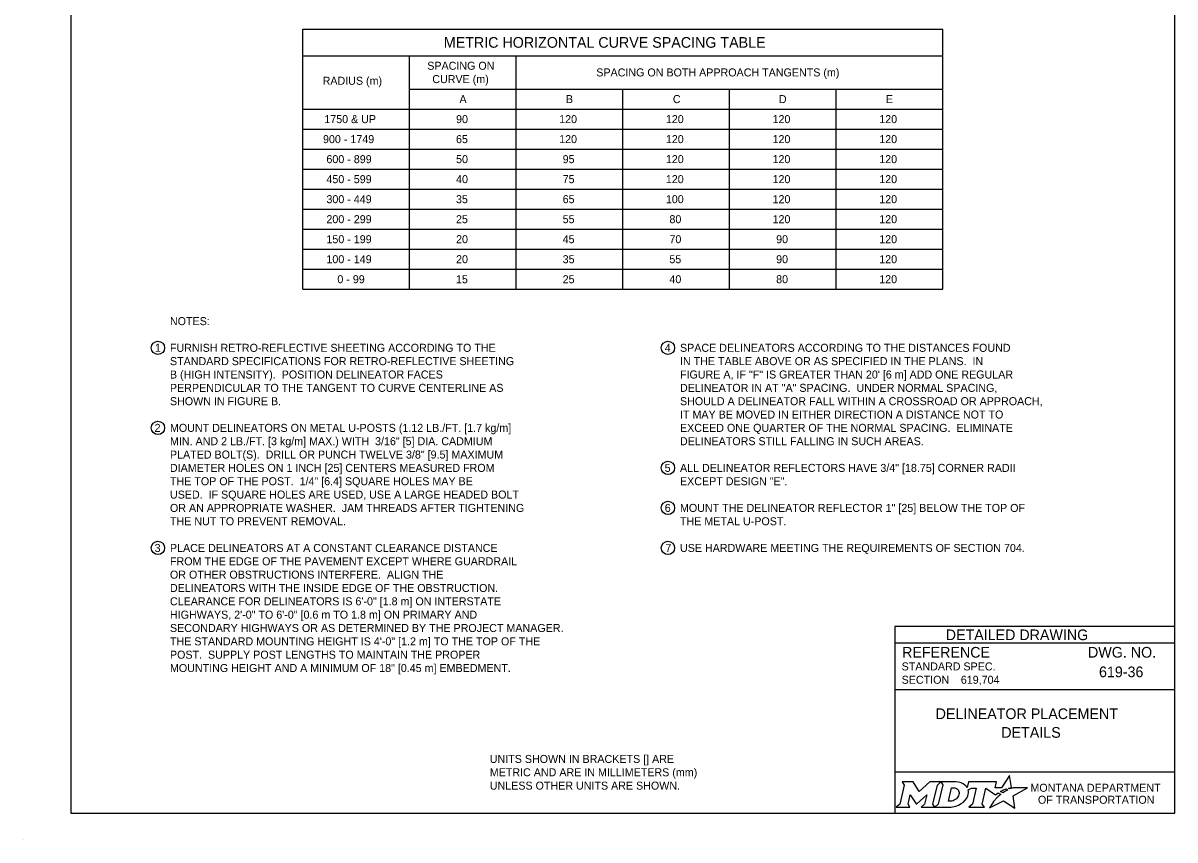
# Model space of a CAD drawing. Extents: x 49991.4 to 50021, y 49987.6 to 50011.4.
# Drawn here: x 49999.98 to 50008.61, y 49999.86 to 50005.99 of the extents above; entities that cross this region are included whole.
import ezdxf

# ---------------------------------------------------------------- set-up
doc = ezdxf.new("R2010")
doc.units = 0
doc.layers.add('Level 1', color=7, linetype='Continuous')
doc.layers.add('Level 2', color=7, linetype='Continuous')

msp = doc.modelspace()

# ---------------------------------------------------------------- linework, layer by layer
at = {"layer": 'Level 1'}
msp.add_line((49999.9766, 49999.8624), (49999.9766, 49999.8624), dxfattribs=at)
msp.add_lwpolyline([(50008.6146, 50011.2628), (50000.3356, 50011.2628), (50000.3356, 50000.0624), (50008.6146, 50000.0624)], close=True, dxfattribs=at)
at = {"layer": 'Level 2'}
for p, q in [((50002.0751, 50005.9401), (50006.8751, 50005.9401)), ((50002.0751, 50003.9901), (50002.0751, 50005.9401)), ((50006.8751, 50003.9901), (50006.8751, 50005.9401)), ((50002.0751, 50005.7401), (50006.8751, 50005.7401)), ((50002.8751, 50003.9901), (50002.8751, 50005.7401)), ((50003.6751, 50003.9901), (50003.6751, 50005.7401)), ((50002.8751, 50005.4901), (50006.8751, 50005.4901)), ((50004.4751, 50003.9901), (50004.4751, 50005.4901)), ((50005.2751, 50003.9901), (50005.2751, 50005.4901)), ((50006.0751, 50003.9901), (50006.0751, 50005.4901)), ((50002.0751, 50005.3401), (50006.8751, 50005.3401)), ((50002.0751, 50005.1901), (50006.8751, 50005.1901)), ((50002.0751, 50005.0401), (50006.8751, 50005.0401)), ((50002.0751, 50004.8901), (50006.8751, 50004.8901)), ((50002.0751, 50004.7401), (50006.8751, 50004.7401)), ((50002.0751, 50004.5901), (50006.8751, 50004.5901)), ((50002.0751, 50004.4401), (50006.8751, 50004.4401)), ((50002.0751, 50004.2901), (50006.8751, 50004.2901)), ((50002.0751, 50004.1401), (50006.8751, 50004.1401)), ((50002.0751, 50003.9901), (50006.8751, 50003.9901)), ((50008.6146, 50001.4624), (50006.5146, 50001.4624)), ((50006.5146, 50001.4624), (50006.5146, 50000.0624)), ((50008.6146, 50001.3374), (50006.5146, 50001.3374)), ((50008.2507, 50001.1223), (50008.2507, 50001.1223)), ((50008.6146, 50000.9874), (50006.5146, 50000.9874)), ((50007.0089, 50001.0629), (50007.0089, 50001.0629)), ((50007.5646, 50000.7383), (50007.5646, 50000.7383)), ((50008.6146, 50000.3693), (50006.5146, 50000.3693))]:
    msp.add_line(p, q, dxfattribs=at)
for points in [[(50006.5701, 50000.2974), (50006.5842, 50000.274), (50006.5507, 50000.1307), (50006.525, 50000.1082), (50006.6266, 50000.1082), (50006.6131, 50000.131), (50006.6293, 50000.2011), (50006.673, 50000.1321), (50006.6783, 50000.1321), (50006.7534, 50000.2016), (50006.737, 50000.1305), (50006.7123, 50000.1085), (50006.8139, 50000.1085), (50006.8001, 50000.1318), (50006.8333, 50000.2742)], [(50006.8333, 50000.2742), (50006.8586, 50000.2974), (50006.7762, 50000.2974), (50006.6966, 50000.2244), (50006.6521, 50000.2971), (50006.5701, 50000.2974)], [(50006.9722, 50000.2974), (50006.8586, 50000.2974), (50006.8733, 50000.2745), (50006.8394, 50000.1307), (50006.8139, 50000.1085), (50006.9245, 50000.1085)], [(50007.3771, 50000.2447), (50007.3668, 50000.2503), (50007.3784, 50000.2531), (50007.39, 50000.2551), (50007.3726, 50000.3452), (50007.3131, 50000.2539), (50007.2658, 50000.2532), (50007.2761, 50000.2973), (50007.0669, 50000.2974), (50007.0568, 50000.2549), (50007.051, 50000.2632)], [(50006.9962, 50000.2107), (50006.995, 50000.2026), (50006.9918, 50000.1933), (50006.9876, 50000.1851), (50006.982, 50000.1776), (50006.9755, 50000.1707), (50006.9676, 50000.1644), (50006.9593, 50000.1597), (50006.9502, 50000.1558), (50006.9411, 50000.1535), (50006.9319, 50000.1526), (50006.916, 50000.1526), (50006.9396, 50000.2526), (50006.9556, 50000.2526), (50006.9632, 50000.252), (50006.9708, 50000.2501), (50006.9774, 50000.2471), (50006.9835, 50000.2429), (50006.9883, 50000.2379), (50006.992, 50000.2319), (50006.9947, 50000.2257), (50006.9963, 50000.2183), (50006.9963, 50000.2153), (50006.9962, 50000.2107)], [(50007.0636, 50000.2383), (50007.0882, 50000.2514), (50007.1251, 50000.2514), (50007.0965, 50000.1309), (50007.069, 50000.1082), (50007.1852, 50000.1082), (50007.1682, 50000.1311), (50007.1964, 50000.2513), (50007.2677, 50000.1996), (50007.2888, 50000.2147), (50007.3085, 50000.2038)], [(50007.2527, 50000.1479), (50007.2374, 50000.1235), (50007.2327, 50000.116), (50007.2269, 50000.1074), (50007.2246, 50000.1031), (50007.3299, 50000.1562), (50007.4138, 50000.1011), (50007.4007, 50000.1938), (50007.5076, 50000.2522), (50007.4583, 50000.253), (50007.4282, 50000.2534), (50007.4074, 50000.2537), (50007.4006, 50000.2522), (50007.3957, 50000.251), (50007.3873, 50000.2487), (50007.3771, 50000.2447)], [(50007.3267, 50000.2171), (50007.3243, 50000.2154), (50007.306, 50000.225), (50007.3163, 50000.2307), (50007.3204, 50000.2329), (50007.329, 50000.2369), (50007.3347, 50000.2395), (50007.3426, 50000.2425), (50007.3499, 50000.2452), (50007.3617, 50000.2378), (50007.3577, 50000.2357), (50007.3531, 50000.2332), (50007.3489, 50000.231), (50007.3439, 50000.2281), (50007.342, 50000.227), (50007.3393, 50000.2254), (50007.3368, 50000.224), (50007.3345, 50000.2224), (50007.3319, 50000.2206), (50007.3292, 50000.2188), (50007.3267, 50000.2171)], [(50006.9702, 50000.1158), (50006.9786, 50000.1184), (50006.9916, 50000.1238), (50007.012, 50000.1348)], [(50007.2666, 50000.164), (50007.2666, 50000.164)]]:
    msp.add_lwpolyline(points, dxfattribs=at)
for centre in [(50000.9883, 50003.551), (50004.8129, 50003.551), (50000.9883, 50002.951), (50004.8129, 50002.651), (50004.8129, 50002.351), (50000.9883, 50002.051), (50004.8129, 50002.051)]:
    msp.add_circle(centre, 0.05, dxfattribs=at)
for centre, radius, start, end in [((50006.9953, 50000.219), 0.0709, 339.53292, 15.85821), ((50006.9513, 50000.2363), 0.1183, 300.91025, 339.13831)]:
    msp.add_arc(centre, radius, start, end, dxfattribs=at)
for centre, major_axis, ratio, start_param, end_param in [((50006.9701, 50000.25), (0.0834, -0.0037), 0.568097, 0.61298, 1.570796), ((50007.0257, 50000.2573), (0.0361, -0.0295), 0.469099, 1.225588, 1.570796), ((50007.2974, 50000.1941), (-0.0112, -0.0097), 0.021651, 3.157348, 6.283185), ((50006.9248, 50000.2568), (0, 0.1484), 0.987302, 3.139398, 3.456847), ((50007.2597, 50000.1559), (-0.00694, -0.00806), 0.008222, 0, 3.137361), ((50007.2764, 50000.1742), (-0.0098, -0.0102), 0.016458, 3.141593, 6.279097)]:
    msp.add_ellipse(centre, major_axis=major_axis, ratio=ratio, start_param=start_param, end_param=end_param, dxfattribs=at)

# ---------------------------------------------------------------- texts
for s, height, p in [('METRIC HORIZONTAL CURVE SPACING TABLE', 0.08, (50003.1317, 50005.8001)), ('SPACING ON', 0.06, (50003.0077, 50005.6351)), ('SPACING ON BOTH APPROACH TANGENTS (m)', 0.06, (50004.2752, 50005.5851)), ('RADIUS (m)', 0.06, (50002.2232, 50005.5226)), ('CURVE (m)', 0.06, (50003.0455, 50005.5351)), ('A', 0.06, (50003.2494, 50005.3851)), ('B', 0.06, (50004.0474, 50005.3851)), ('C', 0.06, (50004.8495, 50005.3851)), ('D', 0.06, (50005.6448, 50005.3851)), ('E', 0.06, (50006.4471, 50005.3851)), ('1750 & UP', 0.06, (50002.2358, 50005.2351)), ('90', 0.06, (50003.2239, 50005.2351)), ('120', 0.06, (50003.997, 50005.2351)), ('120', 0.06, (50004.797, 50005.2351)), ('120', 0.06, (50005.597, 50005.2351)), ('120', 0.06, (50006.397, 50005.2351)), (' 900 - 1749', 0.06, (50002.2038, 50005.0851)), ('65', 0.06, (50003.2233, 50005.0851)), ('120', 0.06, (50003.9969, 50005.0851)), ('120', 0.06, (50004.797, 50005.0851)), ('120', 0.06, (50005.597, 50005.0851)), ('120', 0.06, (50006.397, 50005.0851)), ('600 - 899', 0.06, (50002.2517, 50004.9351)), ('50', 0.06, (50003.2238, 50004.9351)), ('95', 0.06, (50004.0233, 50004.9351)), ('120', 0.06, (50004.797, 50004.9351)), ('120', 0.06, (50005.5969, 50004.9351)), ('120', 0.06, (50006.397, 50004.9351)), ('450 - 599', 0.06, (50002.2517, 50004.7851)), ('40', 0.06, (50003.2239, 50004.7851)), ('75', 0.06, (50004.0233, 50004.7851)), ('120', 0.06, (50004.7969, 50004.7851)), ('120', 0.06, (50005.597, 50004.7851)), ('120', 0.06, (50006.397, 50004.7851)), ('300 - 449', 0.06, (50002.2517, 50004.6351)), ('35', 0.06, (50003.2233, 50004.6351)), ('65', 0.06, (50004.0233, 50004.6351)), ('100', 0.06, (50004.797, 50004.6351)), ('120', 0.06, (50005.597, 50004.6351)), ('120', 0.06, (50006.397, 50004.6351)), ('200 - 299', 0.06, (50002.2517, 50004.4851)), ('25', 0.06, (50003.2233, 50004.4851)), ('55', 0.06, (50004.0233, 50004.4851)), ('80', 0.06, (50004.8239, 50004.4851)), ('120', 0.06, (50005.597, 50004.4851)), ('120', 0.06, (50006.397, 50004.4851)), ('150 - 199', 0.06, (50002.2517, 50004.3351)), ('20', 0.06, (50003.2238, 50004.3351)), ('45', 0.06, (50004.0233, 50004.3351)), ('70', 0.06, (50004.8239, 50004.3351)), ('90', 0.06, (50005.6239, 50004.3351)), ('120', 0.06, (50006.397, 50004.3351)), ('100 - 149', 0.06, (50002.2517, 50004.1851)), ('20', 0.06, (50003.2239, 50004.1851)), ('35', 0.06, (50004.0233, 50004.1851)), ('55', 0.06, (50004.8233, 50004.1851)), ('90', 0.06, (50005.6239, 50004.1851)), ('120', 0.06, (50006.397, 50004.1851)), (' 0 - 99', 0.06, (50002.3115, 50004.0351)), ('15', 0.06, (50003.2233, 50004.0351)), ('25', 0.06, (50004.0233, 50004.0351)), ('40', 0.06, (50004.8238, 50004.0351)), ('80', 0.06, (50005.6239, 50004.0351)), ('120', 0.06, (50006.397, 50004.0351)), ('NOTES:', 0.06, (50001.0783, 50003.721)), ('1', 0.06, (50000.9652, 50003.521)), ('FURNISH RETRO-REFLECTIVE SHEETING ACCORDING TO THE', 0.06, (50001.0783, 50003.521)), ('4', 0.06, (50004.7889, 50003.521)), ('SPACE DELINEATORS ACCORDING TO THE DISTANCES FOUND', 0.06, (50004.9029, 50003.521)), ('STANDARD SPECIFICATIONS FOR RETRO-REFLECTIVE SHEETING', 0.06, (50001.0783, 50003.421)), ('IN THE TABLE ABOVE OR AS SPECIFIED IN THE PLANS.  IN', 0.06, (50004.9029, 50003.421)), ('B (HIGH INTENSITY).  POSITION DELINEATOR FACES', 0.06, (50001.0783, 50003.321)), ('FIGURE A, IF "F" IS GREATER THAN 20\' [6 m] ADD ONE REGULAR', 0.06, (50004.9029, 50003.321)), ('PERPENDICULAR TO THE TANGENT TO CURVE CENTERLINE AS', 0.06, (50001.0783, 50003.221)), ('DELINEATOR IN AT "A" SPACING.  UNDER NORMAL SPACING,', 0.06, (50004.9029, 50003.221)), ('SHOWN IN FIGURE B.', 0.06, (50001.0783, 50003.121)), ('SHOULD A DELINEATOR FALL WITHIN A CROSSROAD OR APPROACH,', 0.06, (50004.9029, 50003.121)), ('IT MAY BE MOVED IN EITHER DIRECTION A DISTANCE NOT TO', 0.06, (50004.9029, 50003.021)), ('2', 0.06, (50000.9631, 50002.921)), ('MOUNT DELINEATORS ON METAL U-POSTS (1.12 LB./FT. [1.7 kg/m]', 0.06, (50001.0783, 50002.921)), ('EXCEED ONE QUARTER OF THE NORMAL SPACING.  ELIMINATE', 0.06, (50004.9029, 50002.921)), ('MIN. AND 2 LB./FT. [3 kg/m] MAX.) WITH  3/16" [5] DIA. CADMIUM', 0.06, (50001.0783, 50002.821)), ('DELINEATORS STILL FALLING IN SUCH AREAS.', 0.06, (50004.9029, 50002.821)), ('PLATED BOLT(S).  DRILL OR PUNCH TWELVE 3/8" [9.5] MAXIMUM ', 0.06, (50001.0783, 50002.721)), ('DIAMETER HOLES ON 1 INCH [25] CENTERS MEASURED FROM ', 0.06, (50001.0783, 50002.621)), ('5', 0.06, (50004.788, 50002.621)), ('ALL DELINEATOR REFLECTORS HAVE 3/4" [18.75] CORNER RADII', 0.06, (50004.9029, 50002.621)), ('THE TOP OF THE POST.  1/4" [6.4] SQUARE HOLES MAY BE', 0.06, (50001.0783, 50002.521)), ('EXCEPT DESIGN "E".', 0.06, (50004.9029, 50002.521)), ('USED.  IF SQUARE HOLES ARE USED, USE A LARGE HEADED BOLT', 0.06, (50001.0783, 50002.421)), ('OR AN APPROPRIATE WASHER.  JAM THREADS AFTER TIGHTENING', 0.06, (50001.0783, 50002.321)), ('6', 0.06, (50004.7884, 50002.321)), ('MOUNT THE DELINEATOR REFLECTOR 1" [25] BELOW THE TOP OF', 0.06, (50004.9029, 50002.321)), ('THE NUT TO PREVENT REMOVAL.', 0.06, (50001.0783, 50002.221)), ('THE METAL U-POST.', 0.06, (50004.9029, 50002.221)), ('3', 0.06, (50000.9631, 50002.021)), ('PLACE DELINEATORS AT A CONSTANT CLEARANCE DISTANCE', 0.06, (50001.0783, 50002.021)), ('7', 0.06, (50004.7935, 50002.021)), ('USE HARDWARE MEETING THE REQUIREMENTS OF SECTION 704.', 0.06, (50004.9029, 50002.021)), ('FROM THE EDGE OF THE PAVEMENT EXCEPT WHERE GUARDRAIL', 0.06, (50001.0783, 50001.921)), ('OR OTHER OBSTRUCTIONS INTERFERE.  ALIGN THE', 0.06, (50001.0783, 50001.821)), ('DELINEATORS WITH THE INSIDE EDGE OF THE OBSTRUCTION.', 0.06, (50001.0783, 50001.721)), ('CLEARANCE FOR DELINEATORS IS 6\'-0" [1.8 m] ON INTERSTATE', 0.06, (50001.0783, 50001.621)), ('HIGHWAYS, 2\'-0" TO 6\'-0" [0.6 m TO 1.8 m] ON PRIMARY AND', 0.06, (50001.0783, 50001.521)), ('SECONDARY HIGHWAYS OR AS DETERMINED BY THE PROJECT MANAGER.', 0.06, (50001.0783, 50001.421)), ('DETAILED DRAWING', 0.0799, (50006.8956, 50001.3599)), ('THE STANDARD MOUNTING HEIGHT IS 4\'-0" [1.2 m] TO THE TOP OF THE', 0.06, (50001.0783, 50001.321)), ('POST.  SUPPLY POST LENGTHS TO MAINTAIN THE PROPER', 0.06, (50001.0783, 50001.221)), ('REFERENCE', 0.08, (50006.5682, 50001.229)), ('DWG. NO.', 0.08, (50007.9624, 50001.229)), ('MOUNTING HEIGHT AND A MINIMUM OF 18" [0.45 m] EMBEDMENT.', 0.06, (50001.0783, 50001.121)), ('STANDARD SPEC.', 0.06, (50006.5649, 50001.133)), ('619-36', 0.08, (50008.0449, 50001.0823)), ('SECTION', 0.06, (50006.5649, 50001.033)), ('619,704', 0.06, (50007.0089, 50001.0329)), ('DELINEATOR PLACEMENT', 0.08, (50006.8201, 50000.7683)), ('DETAILS', 0.08, (50007.3123, 50000.6283)), ('UNITS SHOWN IN BRACKETS [] ARE ', 0.06, (50003.4767, 50000.4396)), ('METRIC AND ARE IN MILLIMETERS (mm) ', 0.06, (50003.4767, 50000.3396)), ('UNLESS OTHER UNITS ARE SHOWN.', 0.06, (50003.4767, 50000.2396)), ('MONTANA DEPARTMENT', 0.06, (50007.5308, 50000.2236)), ('OF TRANSPORTATION', 0.06, (50007.587, 50000.1336))]:
    msp.add_text(s, height=height, dxfattribs=at).set_placement(p)

doc.saveas('drawing.dxf')
